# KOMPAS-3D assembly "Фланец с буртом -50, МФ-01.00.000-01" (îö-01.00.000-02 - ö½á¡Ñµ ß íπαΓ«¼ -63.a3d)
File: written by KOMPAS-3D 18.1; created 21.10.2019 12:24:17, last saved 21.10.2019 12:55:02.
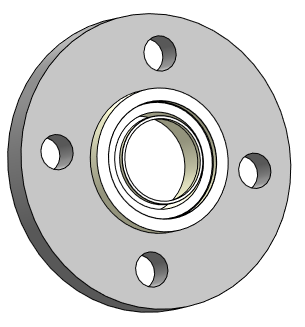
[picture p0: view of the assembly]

Document properties: Полное имя файла: D:\Мембранные насосы\Мембранный электропривод\А302-00.00.000 - ASTRA-302 (МЭ200)\3Д ПВХ\МФ-01.00.000-02 - Фланец с буртом -63.a3d

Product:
- Part/product: Фланец с буртом -50  | designation МФ-01.00.000-01
    Масса: 0.226535
  - Component [detail]: Фланец-50  | designation МФ-00.00.002-01  | Материал: Полипропилен  ГОСТ 26996-86 (density 900 kg/m3); Масса: 0.196337; source file: ..\..\..\..\1 ПКИ 3D\Полипропиленовые фитинги, трубы\FV PPR FE Свободный фланец к фальцевому бурту.m3d
  - Component [detail]: Бурт-50  | designation МБ-00.00.001-01  | Материал: Полипропилен  ГОСТ 26996-86 (density 900 kg/m3); Масса: 0.0301975; source file: ..\..\..\..\1 ПКИ 3D\Полипропиленовые фитинги, трубы\FV PPR Фальцевый бурт 50.m3d

Referenced files in D:\1 ПКИ 3D\Полипропиленовые фитинги, трубы\: FV PPR Фальцевый бурт 50.m3d, FV PPR FE Свободный фланец к фальцевому бурту.m3d
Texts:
  МФ-01.00.000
